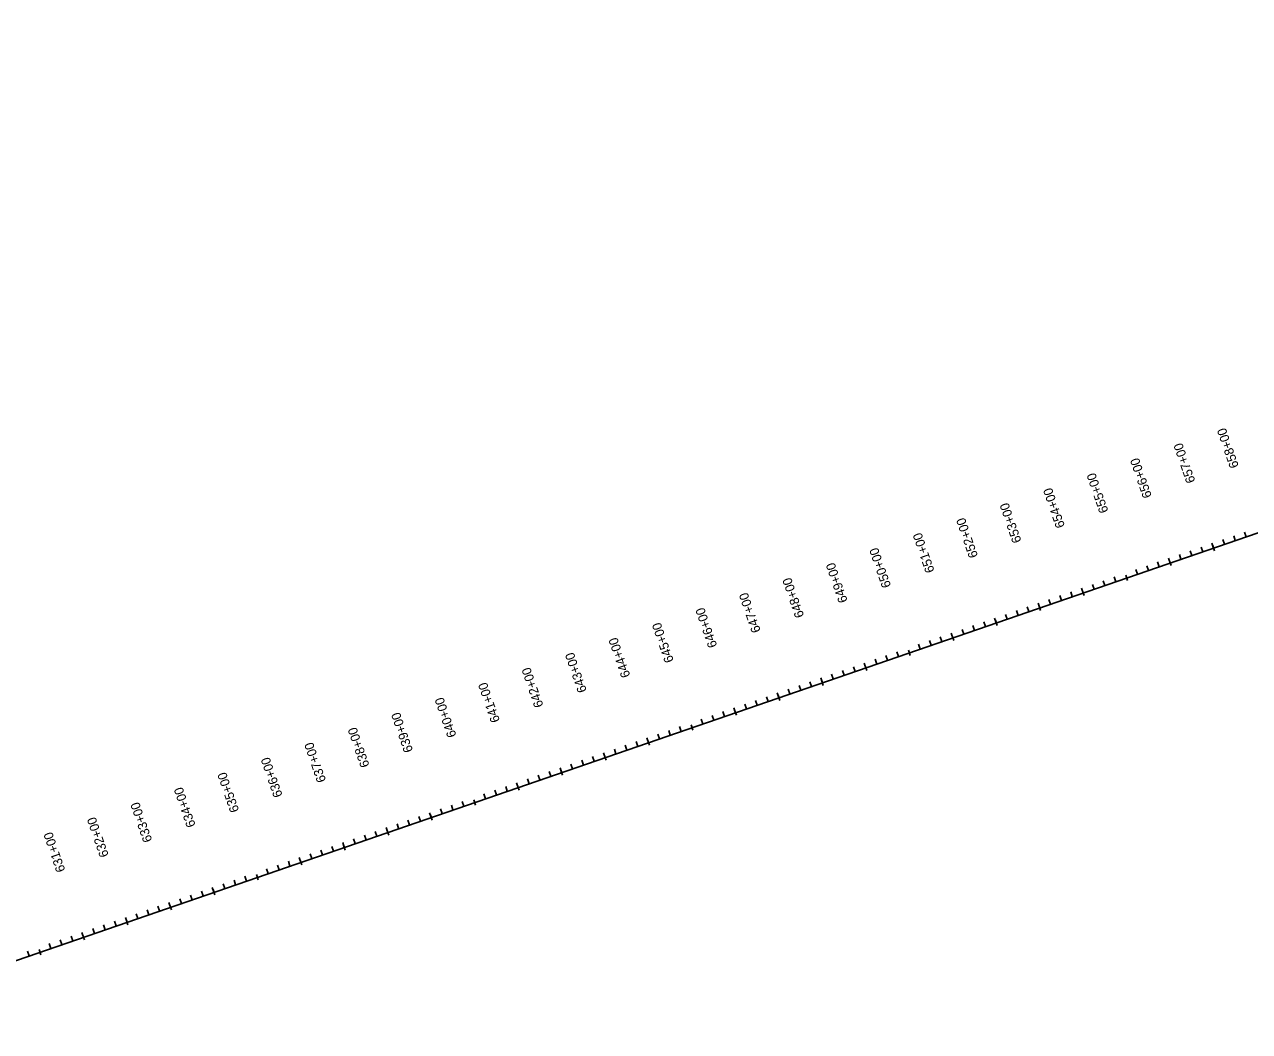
# Model space of a CAD drawing. Extents: x 22693007 to 22771804, y 6223023 to 6251673.
# Drawn here: x 22740482 to 22743147, y 6235735 to 6237925 of the extents above; entities that cross this region are included whole.
import ezdxf

# ---------------------------------------------------------------- set-up
doc = ezdxf.new("R2010")
doc.units = 0
for name, color, linetype in [('Default', 7, 'Continuous'), ('Draft_2', 7, 'Continuous'), ('NamedBoundary', 7, 'Continuous'), ('SheetBorder', 7, 'Continuous')]:
    doc.layers.add(name, color=color, linetype=linetype)

msp = doc.modelspace()

# ---------------------------------------------------------------- linework, layer by layer
at = {"layer": 'Default'}
msp.add_line((22740013.9, 6235734.9), (22746376.2, 6237924.7), dxfattribs=at)
at = {"layer": 'Draft_2'}
for p, q in [((22743068.5, 6236786.2), (22743064.9, 6236796.6)), ((22742973.9, 6236753.7), (22742970.3, 6236764)), ((22742877.4, 6236726.9), (22742881.3, 6236715.4)), ((22742784.8, 6236688.6), (22742781.2, 6236698.9)), ((22742690.2, 6236656.1), (22742686.7, 6236666.4)), ((22742595.7, 6236623.5), (22742592.1, 6236633.8)), ((22742501.1, 6236591), (22742497.6, 6236601.3)), ((22742404.6, 6236564.2), (22742408.6, 6236552.6)), ((22742312, 6236525.9), (22742308.5, 6236536.2)), ((22742217.5, 6236493.3), (22742213.9, 6236503.7)), ((22742122.9, 6236460.8), (22742119.3, 6236471.1)), ((22742028.3, 6236428.2), (22742024.8, 6236438.6)), ((22741931.8, 6236401.5), (22741935.8, 6236389.9)), ((22741839.2, 6236363.1), (22741835.7, 6236373.5)), ((22741744.7, 6236330.6), (22741741.1, 6236340.9)), ((22741650.1, 6236298.1), (22741646.6, 6236308.4)), ((22741555.6, 6236265.5), (22741552, 6236275.8)), ((22741459, 6236238.8), (22741463, 6236227.2)), ((22741366.5, 6236200.4), (22741362.9, 6236210.7)), ((22741271.9, 6236167.9), (22741268.3, 6236178.2)), ((22741177.3, 6236135.3), (22741173.8, 6236145.7)), ((22741082.8, 6236102.8), (22741079.2, 6236113.1)), ((22740986.2, 6236076), (22740990.2, 6236064.5)), ((22740893.7, 6236037.7), (22740890.1, 6236048)), ((22740799.1, 6236005.2), (22740795.6, 6236015.5)), ((22740704.6, 6235972.6), (22740701, 6235982.9)), ((22740610, 6235940.1), (22740606.4, 6235950.4)), ((22740513.5, 6235913.3), (22740517.4, 6235901.7))]:
    msp.add_line(p, q, dxfattribs=at)
at = {"layer": 'NamedBoundary'}
msp.add_line((22740013.9, 6235734.9), (22746376.2, 6237924.7), dxfattribs=at)
at = {"layer": 'SheetBorder'}
for p, q in [((22743139.4, 6236810.6), (22743135.8, 6236821)), ((22743092.1, 6236794.4), (22743088.5, 6236804.7)), ((22743115.7, 6236802.5), (22743112.2, 6236812.8)), ((22742997.5, 6236761.8), (22742994, 6236772.2)), ((22743021.2, 6236770), (22743017.6, 6236780.3)), ((22743044.8, 6236778.1), (22743041.3, 6236788.4)), ((22743066.5, 6236792), (22743070.4, 6236780.4)), ((22742926.6, 6236737.4), (22742923.1, 6236747.7)), ((22742950.3, 6236745.6), (22742946.7, 6236755.9)), ((22742971.9, 6236759.5), (22742975.9, 6236747.9)), ((22742832.1, 6236704.9), (22742828.5, 6236715.2)), ((22742855.7, 6236713), (22742852.2, 6236723.3)), ((22742877.4, 6236726.9), (22742881.3, 6236715.4)), ((22742903, 6236729.3), (22742899.4, 6236739.6)), ((22742761.1, 6236680.5), (22742757.6, 6236690.8)), ((22742782.8, 6236694.4), (22742786.8, 6236682.8)), ((22742808.4, 6236696.7), (22742804.9, 6236707.1)), ((22742688.2, 6236661.8), (22742692.2, 6236650.3)), ((22742713.9, 6236664.2), (22742710.3, 6236674.5)), ((22742737.5, 6236672.3), (22742734, 6236682.7)), ((22742619.3, 6236631.6), (22742615.8, 6236642)), ((22742643, 6236639.8), (22742639.4, 6236650.1)), ((22742666.6, 6236647.9), (22742663, 6236658.2)), ((22742524.8, 6236599.1), (22742521.2, 6236609.4)), ((22742548.4, 6236607.2), (22742544.8, 6236617.6)), ((22742572, 6236615.4), (22742568.5, 6236625.7)), ((22742593.7, 6236629.3), (22742597.7, 6236617.7)), ((22742453.8, 6236574.7), (22742450.3, 6236585)), ((22742477.5, 6236582.8), (22742473.9, 6236593.2)), ((22742499.1, 6236596.8), (22742503.1, 6236585.2)), ((22742382.9, 6236550.3), (22742379.4, 6236560.6)), ((22742404.6, 6236564.2), (22742408.6, 6236552.6)), ((22742430.2, 6236566.6), (22742426.6, 6236576.9)), ((22742288.4, 6236517.7), (22742284.8, 6236528.1)), ((22742310, 6236531.7), (22742314, 6236520.1)), ((22742335.6, 6236534), (22742332.1, 6236544.3)), ((22742359.3, 6236542.1), (22742355.7, 6236552.5)), ((22742241.1, 6236501.5), (22742237.5, 6236511.8)), ((22742264.7, 6236509.6), (22742261.2, 6236519.9)), ((22742146.5, 6236468.9), (22742143, 6236479.2)), ((22742170.2, 6236477.1), (22742166.6, 6236487.4)), ((22742193.8, 6236485.2), (22742190.3, 6236495.5)), ((22742215.5, 6236499.1), (22742219.4, 6236487.5)), ((22742052, 6236436.4), (22742048.4, 6236446.7)), ((22742075.6, 6236444.5), (22742072.1, 6236454.8)), ((22742099.3, 6236452.6), (22742095.7, 6236463)), ((22742120.9, 6236466.6), (22742124.9, 6236455)), ((22741981.1, 6236412), (22741977.5, 6236422.3)), ((22742004.7, 6236420.1), (22742001.1, 6236430.4)), ((22742026.3, 6236434), (22742030.3, 6236422.5)), ((22741910.1, 6236387.6), (22741906.6, 6236397.9)), ((22741931.8, 6236401.5), (22741935.8, 6236389.9)), ((22741957.4, 6236403.8), (22741953.9, 6236414.2)), ((22741837.2, 6236368.9), (22741841.2, 6236357.4)), ((22741862.9, 6236371.3), (22741859.3, 6236381.6)), ((22741886.5, 6236379.4), (22741883, 6236389.7)), ((22741768.3, 6236338.7), (22741764.8, 6236349.1)), ((22741792, 6236346.9), (22741788.4, 6236357.2)), ((22741815.6, 6236355), (22741812, 6236365.3)), ((22741673.8, 6236306.2), (22741670.2, 6236316.5)), ((22741697.4, 6236314.3), (22741693.8, 6236324.7)), ((22741721, 6236322.5), (22741717.5, 6236332.8)), ((22741742.7, 6236336.4), (22741746.7, 6236324.8)), ((22741602.8, 6236281.8), (22741599.3, 6236292.1)), ((22741626.5, 6236289.9), (22741622.9, 6236300.2)), ((22741648.1, 6236303.8), (22741652.1, 6236292.3)), ((22741531.9, 6236257.4), (22741528.4, 6236267.7)), ((22741553.6, 6236271.3), (22741557.6, 6236259.7)), ((22741579.2, 6236273.6), (22741575.6, 6236284)), ((22741437.4, 6236224.8), (22741433.8, 6236235.2)), ((22741459, 6236238.8), (22741463, 6236227.2)), ((22741484.6, 6236241.1), (22741481.1, 6236251.4)), ((22741508.3, 6236249.2), (22741504.7, 6236259.6)), ((22741390.1, 6236208.6), (22741386.5, 6236218.9)), ((22741413.7, 6236216.7), (22741410.2, 6236227)), ((22741295.5, 6236176), (22741292, 6236186.3)), ((22741319.2, 6236184.2), (22741315.6, 6236194.5)), ((22741342.8, 6236192.3), (22741339.3, 6236202.6)), ((22741364.5, 6236206.2), (22741368.4, 6236194.6)), ((22741201, 6236143.5), (22741197.4, 6236153.8)), ((22741224.6, 6236151.6), (22741221.1, 6236161.9)), ((22741248.3, 6236159.7), (22741244.7, 6236170.1)), ((22741269.9, 6236173.7), (22741273.9, 6236162.1)), ((22741130.1, 6236119.1), (22741126.5, 6236129.4)), ((22741153.7, 6236127.2), (22741150.1, 6236137.5)), ((22741175.3, 6236141.1), (22741179.3, 6236129.5)), ((22741059.1, 6236094.7), (22741055.6, 6236105)), ((22741080.8, 6236108.6), (22741084.8, 6236097)), ((22741106.4, 6236110.9), (22741102.9, 6236121.2)), ((22740986.2, 6236076), (22740990.2, 6236064.5)), ((22741011.9, 6236078.4), (22741008.3, 6236088.7)), ((22741035.5, 6236086.5), (22741032, 6236096.8)), ((22740917.3, 6236045.8), (22740913.8, 6236056.2)), ((22740940.9, 6236054), (22740937.4, 6236064.3)), ((22740964.6, 6236062.1), (22740961, 6236072.4)), ((22740822.8, 6236013.3), (22740819.2, 6236023.6)), ((22740846.4, 6236021.4), (22740842.8, 6236031.7)), ((22740870, 6236029.6), (22740866.5, 6236039.9)), ((22740891.7, 6236043.5), (22740895.7, 6236031.9)), ((22740751.8, 6235988.9), (22740748.3, 6235999.2)), ((22740775.5, 6235997), (22740771.9, 6236007.3)), ((22740797.1, 6236010.9), (22740801.1, 6235999.4)), ((22740680.9, 6235964.5), (22740677.4, 6235974.8)), ((22740702.6, 6235978.4), (22740706.6, 6235966.8)), ((22740728.2, 6235980.7), (22740724.6, 6235991.1)), ((22740586.4, 6235931.9), (22740582.8, 6235942.3)), ((22740608, 6235945.8), (22740612, 6235934.3)), ((22740633.6, 6235948.2), (22740630.1, 6235958.5)), ((22740657.3, 6235956.3), (22740653.7, 6235966.7)), ((22740539.1, 6235915.7), (22740535.5, 6235926)), ((22740562.7, 6235923.8), (22740559.2, 6235934.1)), ((22740491.8, 6235899.4), (22740488.3, 6235909.7)), ((22740513.5, 6235913.3), (22740517.4, 6235901.7))]:
    msp.add_line(p, q, dxfattribs=at)

# ---------------------------------------------------------------- texts
at = {"layer": 'Draft_2'}
for s, p in [('655+00', (22742840, 6236866.2)), ('650+00', (22742367.2, 6236703.5)), ('645+00', (22741894.4, 6236540.8)), ('640+00', (22741421.7, 6236378.1)), ('635+00', (22740948.9, 6236215.3))]:
    msp.add_text(s, height=20.04, rotation=108.9929, dxfattribs=at).set_placement(p)
at = {"layer": 'SheetBorder'}
for s, p in [('658+00', (22743123.7, 6236963.9)), ('657+00', (22743029.1, 6236931.3)), ('656+00', (22742934.6, 6236898.8)), ('655+00', (22742840, 6236866.2)), ('654+00', (22742745.4, 6236833.7)), ('653+00', (22742650.9, 6236801.1)), ('652+00', (22742556.3, 6236768.6)), ('651+00', (22742461.8, 6236736.1)), ('650+00', (22742367.2, 6236703.5)), ('649+00', (22742272.7, 6236671)), ('648+00', (22742178.1, 6236638.4)), ('647+00', (22742083.6, 6236605.9)), ('646+00', (22741989, 6236573.3)), ('645+00', (22741894.4, 6236540.8)), ('644+00', (22741799.9, 6236508.2)), ('643+00', (22741705.3, 6236475.7)), ('642+00', (22741610.8, 6236443.2)), ('641+00', (22741516.2, 6236410.6)), ('640+00', (22741421.7, 6236378.1)), ('639+00', (22741327.1, 6236345.5)), ('638+00', (22741232.6, 6236313)), ('637+00', (22741138, 6236280.4)), ('636+00', (22741043.4, 6236247.9)), ('635+00', (22740948.9, 6236215.3)), ('634+00', (22740854.3, 6236182.8)), ('633+00', (22740759.8, 6236150.2)), ('632+00', (22740665.2, 6236117.7)), ('631+00', (22740570.7, 6236085.2))]:
    msp.add_text(s, height=20.04, rotation=108.9929, dxfattribs=at).set_placement(p)

doc.saveas('drawing.dxf')
